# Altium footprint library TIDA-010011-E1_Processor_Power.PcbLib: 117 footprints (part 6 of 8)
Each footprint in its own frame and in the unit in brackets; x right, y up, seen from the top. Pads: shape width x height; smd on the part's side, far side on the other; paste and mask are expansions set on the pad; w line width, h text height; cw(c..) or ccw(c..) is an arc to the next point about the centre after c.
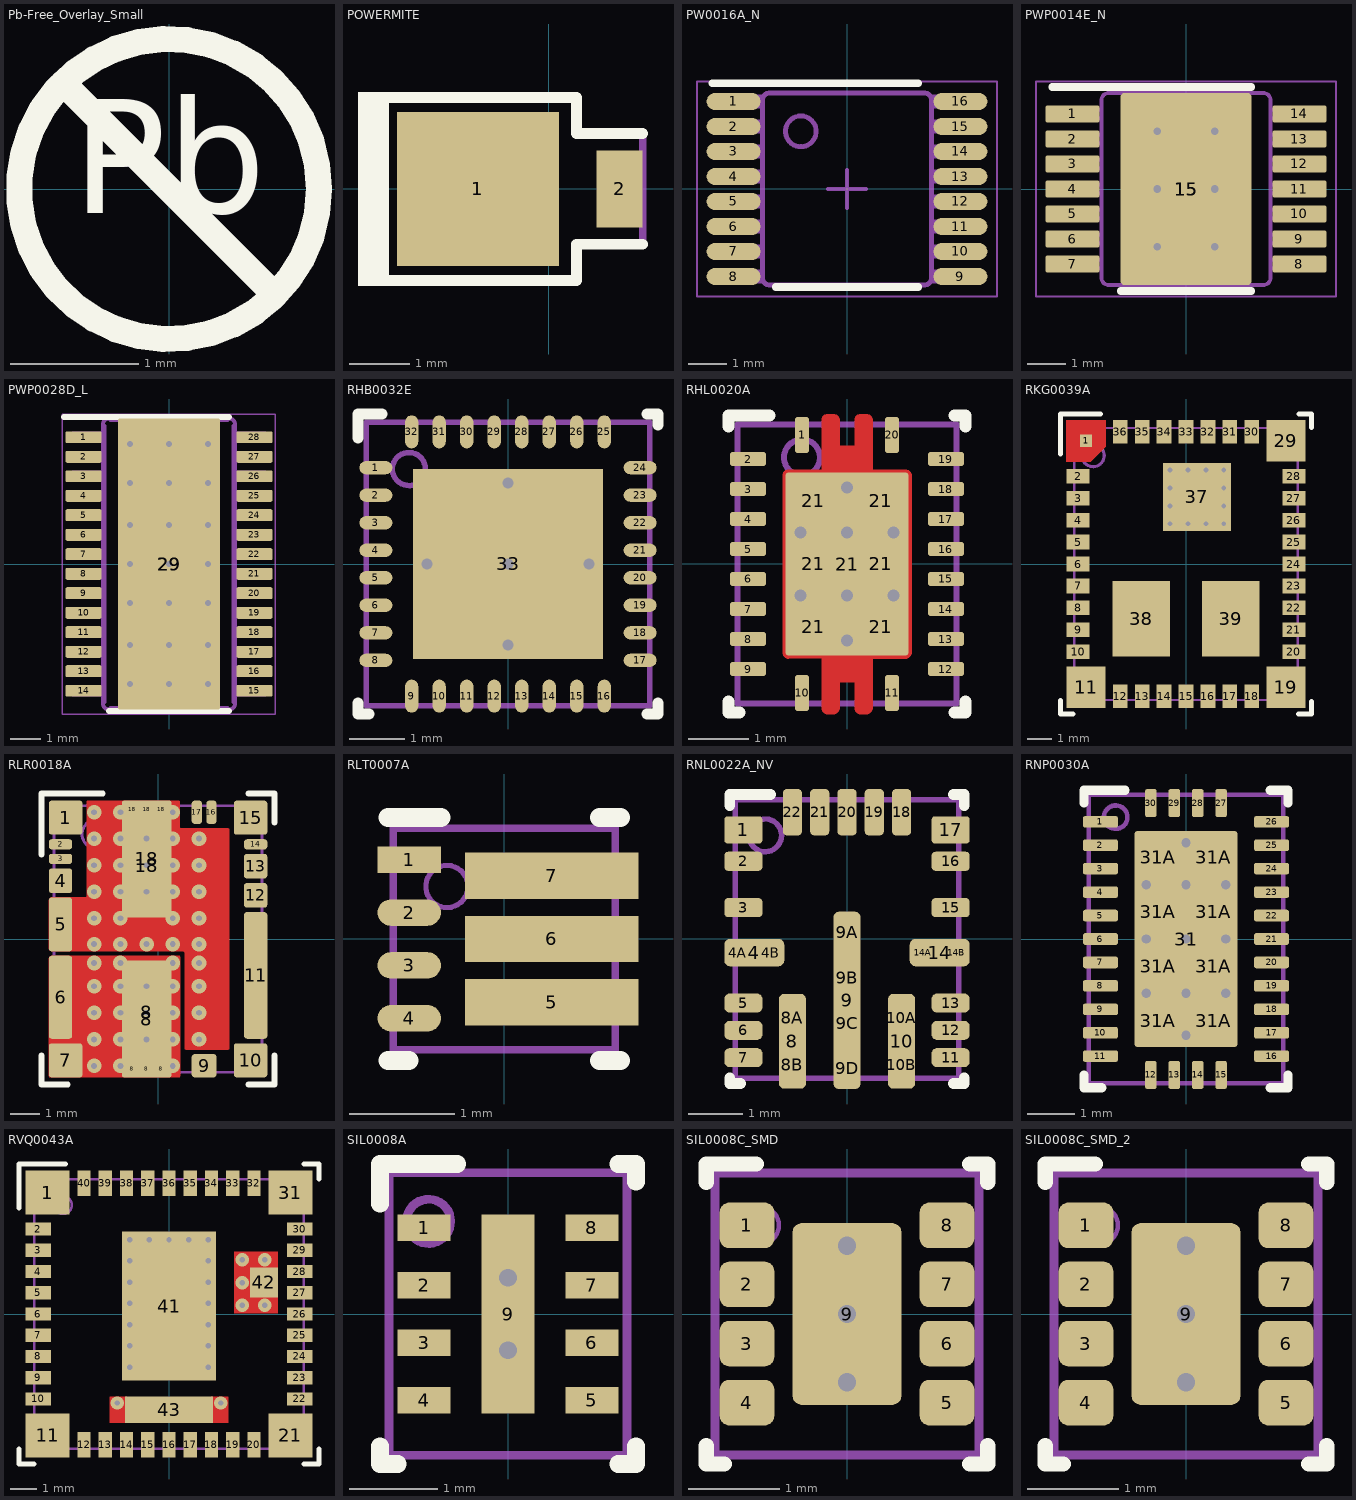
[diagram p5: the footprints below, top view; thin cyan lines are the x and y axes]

## Pb-Free_Overlay_Small [mm]
height 33
Top Overlay:
  circle w0.203: c0,0 r1.168
  lines w0.203: -0.826,0.826 0.826,-0.826
  text "Pb" at -0.752,-0.48 h1.52

## POWERMITE [mil] "On Semi recommended land pattern, 457-04.pdf Rev 04E dated 2008-11-26"
height 45.28
pads (2):
  rect 105x100 smd: 1(-46,0)
  rect 30x50 smd: 2(46,0)
Top Overlay:
  rectangle: -124,-63.02 -104,62.98
  lines w7: -109.7,-59.5 -19,-59.5 18,-59.5 18,-36 61,-36 ; -109.7,59.5 -19,59.5 18,59.5 18,36 61,36
Mechanical 5:
  rectangle: -124,-63.02 -104,62.98
  lines w5: -109.7,-59.5 -19,-59.5 18,-59.5 18,-36 61,-36 61,36 18,36 18,59.5 -19,59.5 -109.7,59.5
  text ".Designator" at -23,8 h20
3D body "PowerMite.stp": height 45.31, standoff 0, extent -94.48,-40.35 59.06,40.36

## PW0016A_N [mm] "TSOP, 16-Leads, Body 5x4.4mm, Pitch 0.65mm, IPC Medium Density"
height 1.2
pads (16):
  oval 1.4x0.45 smd: 1(-2.95,2.275) 2(-2.95,1.625) 3(-2.95,0.975) 4(-2.95,0.325) 5(-2.95,-0.325) 6(-2.95,-0.975) 7(-2.95,-1.625) 8(-2.95,-2.275) 9(2.95,-2.275) 10(2.95,-1.625) 11(2.95,-0.975) 12(2.95,-0.325) 13(2.95,0.325) 14(2.95,0.975) 15(2.95,1.625) 16(2.95,2.275)
Top Overlay:
  lines w0.2: -3.5,2.75 1.85,2.75 ; -1.85,-2.55 1.85,-2.55
Mechanical 5:
  drawing of 202 lines, arcs and shapes, not listed
  text ".Designator" at 0.004,0.787 h0.51
Mechanical 15:
  lines w0.05: -3.9,-2.8 -3.9,2.8 3.9,2.8 3.9,-2.8 -3.9,-2.8
  lines w0.1: -0.5,0 0.5,0 ; 0,-0.5 0,0.5
3D body "PW0016A.stp": height 1, standoff 0, extent -3.21,-2.5 3.21,2.5

## PWP0014E_N [mm] "TSOP, 14-Leads, Body 5x4.4mm, Pitch 0.65mm, Thermal Pad 3x3 mm, IPC Medium Density"
height 1.2
pads (17):
  rrect22% 1.4x0.45 smd: 1(-2.95,1.95) 2(-2.95,1.3) 3(-2.95,0.65) 4(-2.95,0) 5(-2.95,-0.65) 6(-2.95,-1.3) 7(-2.95,-1.95) 8(2.95,-1.95) 9(2.95,-1.3) 10(2.95,-0.65) 11(2.95,0) 12(2.95,0.65) 13(2.95,1.3) 14(2.95,1.95)
  rrect6% 3.4x5 smd paste-2 mask-2: 15(0,0)
  rrect50% 2.46x2.31 on Top Paste: 15(0,0)
  rrect50% 2.46x2.31 on Top Solder: 15(0,0)
via 0.75,-1.5 diameter 0.5 hole 0.2
via -0.75,-1.5 diameter 0.5 hole 0.2
via -0.75,1.5 diameter 0.5 hole 0.2
via 0.75,1.5 diameter 0.5 hole 0.2
via 0.75,0 diameter 0.5 hole 0.2
via -0.75,0 diameter 0.5 hole 0.2
Top Overlay:
  lines w0.2: -3.475,2.65 1.7,2.65 ; -1.7,-2.65 1.7,-2.65
Mechanical 5:
  lines w0.1: -2.2,-2.06 -3.209,-2.06 -3.209,-1.84 -2.2,-1.84 ; -2.2,-1.41 -3.209,-1.41 -3.209,-1.19 -2.2,-1.19 ; -2.2,-0.76 -3.209,-0.76 -3.209,-0.54 -2.2,-0.54 ; -2.2,-0.11 -3.209,-0.11 -3.209,0.11 -2.2,0.11 ; -2.2,0.54 -3.209,0.54 -3.209,0.76 -2.2,0.76 ; -2.2,1.19 -3.209,1.19 -3.209,1.41 -2.2,1.41 ; -2.2,1.84 -3.209,1.84 -3.209,2.06 -2.2,2.06 ; 2.2,-2.06 3.209,-2.06 3.209,-1.84 2.2,-1.84 ; 2.2,-1.41 3.209,-1.41 3.209,-1.19 2.2,-1.19 ; 2.2,-0.76 3.209,-0.76 3.209,-0.54 2.2,-0.54 ; 2.2,-0.11 3.209,-0.11 3.209,0.11 2.2,0.11 ; 2.2,0.54 3.209,0.54 3.209,0.76 2.2,0.76 ; 2.2,1.19 3.209,1.19 3.209,1.41 2.2,1.41 ; 2.2,1.84 3.209,1.84 3.209,2.06 2.2,2.06 ; -2.2,-2.3 ccw(c-2,-2.3) -2,-2.5 2,-2.5 ccw(c2,-2.3) 2.2,-2.3 2.2,2.3 ccw(c2,2.3) 2,2.5 -2,2.5 ccw(c-2,2.3) -2.2,2.3 -2.2,-2.3 ; -1.2,1.1 ccw(c-1.2,1.5) -1.2,1.9 ccw(c-1.2,1.5) -1.2,1.1
  text ".Designator" at -0.914,-0.279 h0.51
Mechanical 15:
  lines w0.05: -3.9,-2.8 -3.9,2.8 3.9,2.8 3.9,-2.8 -3.9,-2.8
  lines w0.1: -0.5,0 0.5,0 ; 0,-0.5 0,0.5
3D body "PWP0014A.stp": height 1, standoff 0, extent -3.209,-2.5 3.209,2.5

## PWP0028D_L [mm] "TSOP, 28-Leads, Body 9.7x4.4mm, Pitch 0.65mm, Exposed Pad, IPC High Density"
height 1.1
pads (31):
  rrect25% 1.2x0.4 smd: 1(-2.85,4.225) 2(-2.85,3.575) 3(-2.85,2.925) 4(-2.85,2.275) 5(-2.85,1.625) 6(-2.85,0.975) 7(-2.85,0.325) 8(-2.85,-0.325) 9(-2.85,-0.975) 10(-2.85,-1.625) 11(-2.85,-2.275) 12(-2.85,-2.925) 13(-2.85,-3.575) 14(-2.85,-4.225) 15(2.85,-4.225) 16(2.85,-3.575) 17(2.85,-2.925) 18(2.85,-2.275) 19(2.85,-1.625) 20(2.85,-0.975) 21(2.85,-0.325) 22(2.85,0.325) 23(2.85,0.975) 24(2.85,1.625) 25(2.85,2.275) 26(2.85,2.925) 27(2.85,3.575) 28(2.85,4.225)
  rrect3% 3.4x9.7 smd paste-1.7 mask-1.7: 29(0,0)
  rrect50% 2.4x6.46 on Top Paste: 29(0,0)
  rrect50% 2.4x6.46 on Top Solder: 29(0,0)
via -1.3,-2.7 diameter 0.5 hole 0.2
via 0,-2.7 diameter 0.5 hole 0.2
via 1.3,-2.7 diameter 0.5 hole 0.2
via -1.3,-4 diameter 0.5 hole 0.2
via 0,-4 diameter 0.5 hole 0.2
via 1.3,-4 diameter 0.5 hole 0.2
via 1.3,-1.3 diameter 0.5 hole 0.2
via 0,-1.3 diameter 0.5 hole 0.2
via -1.3,-1.3 diameter 0.5 hole 0.2
via 1.3,4 diameter 0.5 hole 0.2
via 0,4 diameter 0.5 hole 0.2
via -1.3,4 diameter 0.5 hole 0.2
via 1.3,2.7 diameter 0.5 hole 0.2
via 0,2.7 diameter 0.5 hole 0.2
via -1.3,2.7 diameter 0.5 hole 0.2
via -1.3,0 diameter 0.5 hole 0.2
via -1.3,1.3 diameter 0.5 hole 0.2
via 0,1.3 diameter 0.5 hole 0.2
via 1.3,1.3 diameter 0.5 hole 0.2
via 1.3,0 diameter 0.5 hole 0.2
via 0,0 diameter 0.5 hole 0.2
Top Overlay:
  lines w0.2: -3.5,4.9 2,4.9 ; -2,-4.9 2,-4.9
Mechanical 5:
  drawing of 350 lines, arcs and shapes, not listed
  text ".Designator" at -0.991,-0.203 h0.51
Mechanical 15:
  lines w0.05: -3.55,-5 -3.55,5 3.55,5 3.55,-5 -3.55,-5
  lines w0.1: -0.5,0 0.5,0 ; 0,-0.5 0,0.5
3D body "PWP0028B.stp": height 1, standoff 0, extent -3.21,-4.85 3.21,4.85

## RHB0032E [mm] "QFN, 32-Leads, Body 5x5mm, Pitch 0.5mm, Thermal Pad 3.45x3.45mm, TI Recommended"
height 1
pads (33):
  oval 0.6x0.24 smd: 1(-2.4,1.75) 2(-2.4,1.25) 3(-2.4,0.75) 4(-2.4,0.25) 5(-2.4,-0.25) 6(-2.4,-0.75) 7(-2.4,-1.25) 8(-2.4,-1.75) 17(2.4,-1.75) 18(2.4,-1.25) 19(2.4,-0.75) 20(2.4,-0.25) 21(2.4,0.25) 22(2.4,0.75) 23(2.4,1.25) 24(2.4,1.75)
  oval 0.24x0.6 smd: 9(-1.75,-2.4) 10(-1.25,-2.4) 11(-0.75,-2.4) 12(-0.25,-2.4) 13(0.25,-2.4) 14(0.75,-2.4) 15(1.25,-2.4) 16(1.75,-2.4) 25(1.75,2.4) 26(1.25,2.4) 27(0.75,2.4) 28(0.25,2.4) 29(-0.25,2.4) 30(-0.75,2.4) 31(-1.25,2.4) 32(-1.75,2.4)
  rect 3.45x3.45 smd paste-1.725: 33(0,0)
via 0,-1.475 diameter 0.5 hole 0.2
via 1.475,0 diameter 0.5 hole 0.2
via 0,0 diameter 0.5 hole 0.2
via -1.475,0 diameter 0.5 hole 0.2
via 0,1.475 diameter 0.5 hole 0.2
Top Overlay:
  lines w0.2: -2.725,-2.525 -2.725,-2.725 -2.525,-2.725 ; -2.725,2.29 -2.725,2.725 -2.29,2.725 ; 2.525,-2.725 2.725,-2.725 2.725,-2.525 ; 2.525,2.725 2.725,2.725 2.725,2.525
Top Paste:
  rectangle: 0.1,0.1 1.586,1.586
  region: -0.1,1.586 -1.586,1.586 -1.586,0.1 -0.1,0.1
  region: -0.1,-0.1 -1.586,-0.1 -1.586,-1.586 -0.1,-1.586
  rectangle: 0.1,-1.586 1.586,-0.1
Mechanical 5:
  circle w0.1: c-1.8,1.725 r0.3
  lines w0.1: -2.575,-2.575 2.575,-2.575 2.575,2.575 -2.575,2.575 -2.575,-2.575
  text ".Designator" at -1.854,-0.508 h0.51
3D body: height 1, standoff 0, extent -2.575,-2.575 2.575,2.575
3D body: height 1.01, standoff 0.5, extent -2.099,1.426 -1.501,2.024

## RHL0020A [mm] "QFN, 20-Leads, Body 4.5x3.5mm, Pitch 0.5mm, Thermal Pad 3.05x2.05mm, TI Recommended"
height 1
pads (27):
  rrect42% 0.24x0.6 smd: 1(-0.75,2.15) 10(-0.75,-2.15) 11(0.75,-2.15) 20(0.75,2.15)
  rrect42% 0.6x0.24 smd: 2(-1.65,1.75) 3(-1.65,1.25) 4(-1.65,0.75) 5(-1.65,0.25) 6(-1.65,-0.25) 7(-1.65,-0.75) 8(-1.65,-1.25) 9(-1.65,-1.75) 12(1.65,-1.75) 13(1.65,-1.25) 14(1.65,-0.75) 15(1.65,-0.25) 16(1.65,0.25) 17(1.65,0.75) 18(1.65,1.25) 19(1.65,1.75)
  rrect50% 0.92x0.85 on Top Paste: 21(-0.56,-1.05) 21(-0.56,0) 21(-0.56,1.05) 21(0.56,-1.05) 21(0.56,0) 21(0.56,1.05)
  rrect5% 2.05x3.05 smd paste-2 mask+0: 21(0,0)
via 0,0.525 diameter 0.5 hole 0.2
via -0.775,0.525 diameter 0.5 hole 0.2
via 0,1.275 diameter 0.5 hole 0.2
via 0.775,0.525 diameter 0.5 hole 0.2
via 0,-1.275 diameter 0.5 hole 0.2
via 0.775,-0.525 diameter 0.5 hole 0.2
via -0.775,-0.525 diameter 0.5 hole 0.2
via 0,-0.525 diameter 0.5 hole 0.2
Top Layer:
  region: -0.975,-1.575 -0.425,-1.575 -0.425,-2.4 -0.425,-2.42 -0.41,-2.457 -0.382,-2.485 -0.345,-2.5 -0.325,-2.5 -0.225,-2.5 -0.205,-2.5 -0.168,-2.485 -0.14,-2.457 -0.125,-2.42 -0.125,-2.4 -0.125,-1.975 0.125,-1.975 0.125,-2.4 0.125,-2.42 0.14,-2.457 0.168,-2.485 0.205,-2.5 0.225,-2.5 0.325,-2.5 0.345,-2.5 0.382,-2.485 0.41,-2.457 0.425,-2.42 0.425,-2.4 0.425,-1.575 0.975,-1.575 0.995,-1.575 1.032,-1.56 1.06,-1.532 1.075,-1.495 1.075,-1.475 1.075,1.475 1.075,1.495 1.06,1.532 1.032,1.56 0.995,1.575 0.975,1.575 0.425,1.575 0.425,2.4 0.425,2.42 0.41,2.457 0.382,2.485 0.345,2.5 0.325,2.5 0.225,2.5 0.205,2.5 0.168,2.485 0.14,2.457 0.125,2.42 0.125,2.4 0.125,1.975 -0.125,1.975 -0.125,2.4 -0.125,2.42 -0.14,2.457 -0.168,2.485 -0.205,2.5 -0.225,2.5 -0.325,2.5 -0.345,2.5 -0.382,2.485 -0.41,2.457 -0.425,2.42 -0.425,2.4 -0.425,1.575 -0.975,1.575 -0.995,1.575 -1.032,1.56 -1.06,1.532 -1.075,1.495 -1.075,1.475 -1.075,-1.475 -1.075,-1.495 -1.06,-1.532 -1.032,-1.56 -0.995,-1.575
Top Overlay:
  lines w0.2: -1.975,-2.29 -1.975,-2.475 -1.79,-2.475 ; -1.975,2.29 -1.975,2.475 -1.29,2.475 ; 1.79,-2.475 1.975,-2.475 1.975,-2.29 ; 1.79,2.475 1.975,2.475 1.975,2.29
Top Paste:
  region: -0.325,-2.45 -0.335,-2.45 -0.353,-2.442 -0.367,-2.428 -0.375,-2.41 -0.375,-2.4 -0.375,-1.725 -0.375,-1.715 -0.367,-1.697 -0.353,-1.683 -0.335,-1.675 -0.325,-1.675 0.325,-1.675 0.335,-1.675 0.353,-1.683 0.367,-1.697 0.375,-1.715 0.375,-1.725 0.375,-2.4 0.375,-2.41 0.367,-2.428 0.353,-2.442 0.335,-2.45 0.325,-2.45 0.225,-2.45 0.215,-2.45 0.197,-2.442 0.183,-2.428 0.175,-2.41 0.175,-2.4 0.175,-1.925 -0.175,-1.925 -0.175,-2.4 -0.175,-2.41 -0.183,-2.428 -0.197,-2.442 -0.215,-2.45 -0.225,-2.45
  region: -0.325,2.45 -0.335,2.45 -0.353,2.442 -0.367,2.428 -0.375,2.41 -0.375,2.4 -0.375,1.725 -0.375,1.715 -0.367,1.697 -0.353,1.683 -0.335,1.675 -0.325,1.675 0.325,1.675 0.335,1.675 0.353,1.683 0.367,1.697 0.375,1.715 0.375,1.725 0.375,2.4 0.375,2.41 0.367,2.428 0.353,2.442 0.335,2.45 0.325,2.45 0.225,2.45 0.215,2.45 0.197,2.442 0.183,2.428 0.175,2.41 0.175,2.4 0.175,1.925 -0.175,1.925 -0.175,2.4 -0.175,2.41 -0.183,2.428 -0.197,2.442 -0.215,2.45 -0.225,2.45
Mechanical 5:
  circle w0.1: c-0.75,1.775 r0.3
  lines w0.1: -1.825,-2.325 1.825,-2.325 1.825,2.325 -1.825,2.325 -1.825,-2.325
  text ".Designator" at 0.56,-0.021 h0.51
3D body "RHL0020A.stp": height 1.01, standoff 0.01, extent -1.75,-2.25 1.75,2.25

## RKG0039A [mm]
height 2.9
pads (39):
  rect 0.5x0.5 smd paste-0.25: 1(-4.1,5.05)
  rect 0.95x0.6 smd paste-0.025: 2(-4.425,3.6) 3(-4.425,2.7) 4(-4.425,1.8) 5(-4.425,0.9) 6(-4.425,0) 7(-4.425,-0.9) 8(-4.425,-1.8) 9(-4.425,-2.7) 10(-4.425,-3.6) 20(4.425,-3.6) 21(4.425,-2.7) 22(4.425,-1.8) 23(4.425,-0.9) 24(4.425,0) 25(4.425,0.9) 26(4.425,1.8) 27(4.425,2.7) 28(4.425,3.6)
  rect 1.6x1.7 smd paste-0.8: 11(-4.1,-5.05) 19(4.1,-5.05) 29(4.1,5.05)
  rect 0.6x0.95 smd paste-0.025: 12(-2.7,-5.425) 13(-1.8,-5.425) 14(-0.9,-5.425) 15(0,-5.425) 16(0.9,-5.425) 17(1.8,-5.425) 18(2.7,-5.425) 30(2.7,5.425) 31(1.8,5.425) 32(0.9,5.425) 33(0,5.425) 34(-0.9,5.425) 35(-1.8,5.425) 36(-2.7,5.425)
  rect 2.8x2.8 smd paste-1.387 mask-0.6: 37(0.45,2.75)
  rect 2.35x3.1 smd paste-1.537: 38(-1.83,-2.25) 39(1.84,-2.25)
via 0.817,1.65 diameter 0.5 hole 0.2
via 0.083,1.65 diameter 0.5 hole 0.2
via 1.55,3.117 diameter 0.5 hole 0.2
via 1.55,2.383 diameter 0.5 hole 0.2
via -0.65,3.117 diameter 0.5 hole 0.2
via -0.65,2.383 diameter 0.5 hole 0.2
via 0.083,3.85 diameter 0.5 hole 0.2
via 0.817,3.85 diameter 0.5 hole 0.2
via -0.65,1.65 diameter 0.5 hole 0.2
via -0.65,3.85 diameter 0.5 hole 0.2
via 1.55,3.85 diameter 0.5 hole 0.2
via 1.55,1.65 diameter 0.5 hole 0.2
Top Layer:
  region: -4.9,5.9 -3.3,5.9 -3.3,4.8 -3.9,4.2 -4.9,4.2
Top Overlay:
  lines w0.2: -5.15,-5.6 -5.15,-6.15 -4.625,-6.15 ; -5.15,4.5 -5.15,6.15 -3.5,6.15 ; 4.6,-6.15 5.15,-6.15 5.15,-5.625 ; 4.625,6.15 5.15,6.15 5.15,5.6
Top Paste:
  region: -3.325,-4.228 -4.565,-4.228 -4.565,-5.7 -3.325,-5.7
  rectangle: 3.325,-5.7 4.565,-4.228
  rectangle: 0.6,2.9 1.22,3.52
  region: 0.3,3.52 -0.32,3.52 -0.32,2.9 0.3,2.9
  region: 0.3,2.6 -0.32,2.6 -0.32,1.98 0.3,1.98
  rectangle: 0.6,1.98 1.22,2.6
  rectangle: 1.99,-2.1 2.88,-0.85
  region: 1.69,-0.85 0.8,-0.85 0.8,-2.1 1.69,-2.1
  region: 1.69,-2.4 0.8,-2.4 0.8,-3.65 1.69,-3.65
  rectangle: 1.99,-3.65 2.88,-2.4
  rectangle: -1.68,-2.1 -0.79,-0.85
  region: -1.98,-0.85 -2.87,-0.85 -2.87,-2.1 -1.98,-2.1
  region: -1.98,-2.4 -2.87,-2.4 -2.87,-3.65 -1.98,-3.65
  rectangle: -1.68,-3.65 -0.79,-2.4
  rectangle: 3.325,4.228 4.565,5.7
  region: -4.565,5.7 -3.325,5.7 -3.325,4.818 -3.915,4.228 -4.565,4.228
Mechanical 5:
  circle w0.127: c-3.81,4.445 r0.458
  lines w0.1: -4.575,-5.575 4.575,-5.575 4.575,5.575 -4.575,5.575 -4.575,-5.575
  text ".Designator" at 0.411,0.15 h0.51
3D body: height 2.9, standoff 0, extent -4.574,-5.574 4.574,5.574
3D body: height 2.91, standoff 2, extent -4.267,3.988 -3.353,4.902

## RLR0018A [mm] "B2QFN, Body 7x9mm"
height 4.1
pads (60):
  rrect17% 1.15x1.17 smd paste-1.15 mask-1.15: 1(-3.175,4.165) 7(-3.175,-4.165) 10(3.175,-4.165) 15(3.175,4.165)
  rrect57% 0.8x0.35 smd paste-0.05 mask-0.05: 2(-3.35,3.25) 3(-3.35,2.75) 14(3.35,3.25)
  rrect25% 0.8x0.85 smd paste-0.4 mask-0.4: 4(-3.35,2) 12(3.35,1.5) 13(3.35,2.5)
  rrect25% 0.8x1.85 smd paste-0.4 mask-0.4: 5(-3.35,0.5)
  rrect25% 0.8x2.85 smd paste-0.4 mask-0.4: 6(-3.35,-2)
  rrect50% 0.25x0.5 on Top Solder: 8(-0.895,-4.45) 8(-0.395,-4.45) 8(0.105,-4.45) 18(-0.895,4.45) 18(-0.395,4.45) 18(0.105,4.45)
  rrect8% 1.7x4.005 smd paste-2 mask-2: 8(-0.395,-2.748) 18(-0.395,2.748)
  rrect50% 1.6x3.48 on Top Solder: 8(-0.395,-2.521) 18(-0.395,2.519)
  rrect25% 0.85x0.8 smd paste-0.4 mask-0.4: 9(1.58,-4.35)
  rrect25% 0.8x4.35 smd paste-0.4 mask-0.4: 11(3.35,-1.25)
  rrect57% 0.35x0.8 smd paste-0.05 mask-0.05: 16(1.83,4.35) 17(1.33,4.35)
  rrect50% 0.265x0.25 on Top Paste: ""(-3.568,-3.75) ""(-3.568,3.75) ""(3.568,-3.75) ""(3.568,3.75)
  rrect50% 0.585x0.61 on Top Paste: ""(-2.943,-3.93) ""(-2.943,3.93) ""(2.943,-3.93) ""(2.943,3.93)
  rrect50% 0.25x0.265 on Top Paste: ""(-2.775,-4.568) ""(-2.775,4.568) ""(-0.895,-4.568) ""(-0.895,4.568) ""(-0.395,-4.568) ""(-0.395,4.568) ""(0.105,-4.568) ""(0.105,4.568) ""(2.775,-4.568) ""(2.775,4.568)
  rrect50% 0.67x0.71 on Top Paste: ""(-0.83,-3.9) ""(-0.83,-2.99) ""(-0.83,-2.08) ""(-0.83,-1.17) ""(-0.83,1.17) ""(-0.83,2.08) ""(-0.83,2.99) ""(-0.83,3.9) ""(0.04,-3.9) ""(0.04,-2.99) ""(0.04,-2.08) ""(0.04,-1.17) ""(0.04,1.17) ""(0.04,2.08) ""(0.04,2.99) ""(0.04,3.9)
via -2.195,-3.445 diameter 0.5 hole 0.2
via 1.405,-0.825 diameter 0.5 hole 0.2
via 1.405,-2.535 diameter 0.5 hole 0.2
via 1.405,-1.625 diameter 0.5 hole 0.2
via 1.405,-3.445 diameter 0.5 hole 0.2
via -2.195,-4.355 diameter 0.5 hole 0.2
via -2.195,-2.535 diameter 0.5 hole 0.2
via 1.405,3.445 diameter 0.5 hole 0.2
via 1.405,1.625 diameter 0.5 hole 0.2
via 1.405,2.535 diameter 0.5 hole 0.2
via 1.405,0.715 diameter 0.5 hole 0.2
via 1.405,-0.175 diameter 0.5 hole 0.2
via -2.195,3.445 diameter 0.5 hole 0.2
via -2.195,1.625 diameter 0.5 hole 0.2
via -2.195,2.535 diameter 0.5 hole 0.2
via -2.195,0.715 diameter 0.5 hole 0.2
via 0.505,0.715 diameter 0.5 hole 0.2
via -1.295,0.715 diameter 0.5 hole 0.2
via -1.295,2.535 diameter 0.5 hole 0.2
via -1.295,1.625 diameter 0.5 hole 0.2
via -1.295,3.445 diameter 0.5 hole 0.2
via 0.505,3.445 diameter 0.5 hole 0.2
via -0.395,3.445 diameter 0.5 hole 0.2
via -1.295,-3.445 diameter 0.5 hole 0.2
via -1.295,-1.625 diameter 0.5 hole 0.2
via -1.295,-2.535 diameter 0.5 hole 0.2
via 0.505,4.35 diameter 0.5 hole 0.2
via -1.295,4.35 diameter 0.5 hole 0.2
via -2.195,4.35 diameter 0.5 hole 0.2
via -1.295,-4.355 diameter 0.5 hole 0.2
via 0.505,-4.355 diameter 0.5 hole 0.2
via -2.195,-1.625 diameter 0.5 hole 0.2
via -1.295,-0.175 diameter 0.5 hole 0.2
via -2.195,-0.175 diameter 0.5 hole 0.2
via 0.505,-0.175 diameter 0.5 hole 0.2
via 0.505,-3.445 diameter 0.5 hole 0.2
via 0.505,-1.625 diameter 0.5 hole 0.2
via 0.505,-2.535 diameter 0.5 hole 0.2
via -1.295,-0.825 diameter 0.5 hole 0.2
via -2.195,-0.825 diameter 0.5 hole 0.2
via 0.505,1.625 diameter 0.5 hole 0.2
via -0.395,2.535 diameter 0.5 hole 0.2
via 0.505,2.535 diameter 0.5 hole 0.2
via -0.395,1.625 diameter 0.5 hole 0.2
via 0.505,-0.825 diameter 0.5 hole 0.2
via -0.395,-0.175 diameter 0.5 hole 0.2
via -0.395,-1.625 diameter 0.5 hole 0.2
via -0.395,-2.535 diameter 0.5 hole 0.2
via -0.395,-3.445 diameter 0.5 hole 0.2
Top Layer:
  region: -3.7,-4.75 -3.71,-4.75 -3.728,-4.742 -3.742,-4.728 -3.75,-4.71 -3.75,-4.7 -3.75,-0.675 -3.75,-0.655 -3.735,-0.618 -3.707,-0.59 -3.67,-0.575 -3.65,-0.575 0.71,-0.575 0.72,-0.575 0.738,-0.583 0.752,-0.597 0.76,-0.615 0.76,-0.625 0.76,-4.7 0.76,-4.71 0.752,-4.728 0.738,-4.742 0.72,-4.75 0.71,-4.75
  region: -3.65,-0.425 -3.67,-0.425 -3.707,-0.41 -3.735,-0.382 -3.75,-0.345 -3.75,-0.325 -3.75,1.325 -3.75,1.345 -3.735,1.382 -3.707,1.41 -3.67,1.425 -3.65,1.425 -2.5,1.425 -2.49,1.426 -2.472,1.433 -2.458,1.447 -2.451,1.465 -2.45,1.475 -2.45,4.7 -2.45,4.71 -2.442,4.728 -2.428,4.742 -2.41,4.75 -2.4,4.75 0.7,4.75 0.71,4.75 0.728,4.742 0.742,4.728 0.75,4.71 0.75,4.7 0.75,3.85 0.751,3.84 0.758,3.822 0.772,3.808 0.79,3.801 0.8,3.8 2.4,3.8 2.41,3.8 2.428,3.792 2.442,3.778 2.45,3.76 2.45,3.75 2.45,-3.75 2.45,-3.76 2.442,-3.778 2.428,-3.792 2.41,-3.8 2.4,-3.8 0.96,-3.8 0.95,-3.8 0.932,-3.792 0.918,-3.778 0.91,-3.76 0.91,-3.75 0.91,-0.475 0.909,-0.465 0.902,-0.447 0.888,-0.434 0.87,-0.426 0.86,-0.425
Top Overlay:
  lines w0.2: -4,-4 -4,-5 -3.1,-5 ; -4,2.9 -4,5 -1.9,5 ; 3.1,-5 4,-5 4,-4 ; 3.1,5 4,5 4,4
Top Paste:
  drawing of 7 lines, arcs and shapes, not listed
Top Solder:
  drawing of 11 lines, arcs and shapes, not listed
Mechanical 5:
  circle w0.1: c-2.1,3.6 r0.51
  lines w0.1: -3.575,-4.575 3.575,-4.575 3.575,4.575 -3.575,4.575 -3.575,-4.575
  text ".Designator" at -1.115,-0.501 h0.51
3D body: height 4.1, standoff 0, extent -3.575,-4.575 3.575,4.575
3D body: height 4.1, standoff 3.9, extent -2.609,3.091 -1.591,4.109

## RLT0007A [mm] "TI"
height 1
pads (7):
  rect 0.6x0.25 smd paste-0.2: 1(-0.9,0.75)
  oval 0.6x0.25 smd paste-0.2: 2(-0.9,0.25) 3(-0.9,-0.25) 4(-0.9,-0.75)
  rect 1.64x0.44 smd paste-0.22 mask-0.07: 5(0.45,-0.6) 6(0.45,0) 7(0.45,0.6)
Top Overlay:
  lines w0.18: -1.1,-1.15 -0.9,-1.15 ; -1.1,1.15 -0.6,1.15 ; 0.9,-1.15 1.1,-1.15 ; 0.9,1.15 1.1,1.15
Top Paste:
  circle w0.11: c-0.705,-0.75 r0.05
  circle w0.11: c-1.095,-0.75 r0.05
  circle w0.11: c-0.706,-0.25 r0.05
  circle w0.11: c-1.095,-0.25 r0.05
  circle w0.11: c-0.705,0.25 r0.05
  circle w0.11: c-1.095,0.25 r0.05
  rectangle: -0.3,0.45 0.35,0.75
  rectangle: -0.3,-0.15 0.35,0.15
  rectangle: -1.2,0.645 -0.6,0.855
  rectangle: -1.102,-0.855 -0.702,-0.645
  rectangle: -1.105,-0.355 -0.705,-0.145
  rectangle: -1.102,0.145 -0.702,0.355
  rectangle: 0.551,0.45 1.201,0.75
  rectangle: 0.55,-0.15 1.2,0.15
  rectangle: -0.3,-0.75 0.35,-0.45
  rectangle: 0.55,-0.75 1.2,-0.45
Mechanical 5:
  circle w0.05: c-0.543,0.497 r0.2
  lines w0.07: -1.05,-1.05 -1.05,1.05 1.05,1.05 1.05,-1.05 -1.05,-1.05
  text ".Designator" at -0.406,-0.388 h0.51
3D body "RLT0007A.stp": height 1, standoff 0, extent -1,-1 1,1

## RNL0022A_NV [mm] "VQFN, 22 pin, 0.5 mm pitch"
height 0.9
pads (34):
  rrect25% 0.7x0.5 smd paste-0.05 mask-0.05: 1(-1.9,2) 17(1.9,2)
  rrect40% 0.7x0.35 smd paste-0.05 mask-0.05: 2(-1.9,1.425) 3(-1.9,0.575) 15(1.9,0.575) 16(1.9,1.425)
  rrect40% 1.1x0.5 smd paste-0.25 mask-0.05: 4(-1.7,-0.25) 14(1.7,-0.25)
  rrect50% 0.4x0.4 on Top Paste: 4A(-2,-0.25) 4B(-1.4,-0.25) 14A(1.4,-0.25) 14B(2,-0.25)
  rrect57% 0.7x0.35 smd paste-0.05 mask-0.05: 5(-1.9,-1.175) 6(-1.9,-1.675) 7(-1.9,-2.175) 11(1.9,-2.175) 12(1.9,-1.675) 13(1.9,-1.175)
  rrect40% 0.5x1.74 smd paste-0.25 mask-0.05: 8(-1,-1.875) 10(1,-1.875)
  rrect50% 0.4x0.66 on Top Paste: 8A(-1,-1.445) 8B(-1,-2.305) 10A(1,-1.445) 10B(1,-2.305)
  rrect40% 0.5x3.25 smd paste-0.25 mask-0.05: 9(0,-1.125)
  rrect50% 0.4x0.63 on Top Paste: 9A(0,0.12) 9B(0,-0.71) 9C(0,-1.54) 9D(0,-2.37)
  rrect40% 0.35x0.85 smd paste-0.05 mask-0.05: 18(1,2.325) 19(0.5,2.325) 20(0,2.325) 21(-0.5,2.325) 22(-1,2.325)
Top Overlay:
  lines w0.2: -2.15,-2.55 -2.15,-2.65 -1.95,-2.65 ; -2.15,2.45 -2.15,2.65 -1.4,2.65 ; 1.95,-2.65 2.15,-2.65 2.15,-2.55 ; 1.95,2.65 2.15,2.65 2.15,2.45
Mechanical 5:
  circle w0.1: c-1.5,1.9 r0.3
  lines w0.1: -2.05,-2.55 2.05,-2.55 2.05,2.55 -2.05,2.55 -2.05,-2.55
  text ".Designator" at -1.524,-0.508 h0.51
3D body "RNL0022A.stp": height 0.9, standoff 0, extent -2,-2.5 2,2.5

## RNP0030A [mm] "QFN, 30-Leads, Body 6x4mm, Pitch 0.5mm, Thermal Pad 4.6x2.2mm"
height 0.8
pads (39):
  rrect40% 0.75x0.25 smd: 1(-1.825,2.5) 2(-1.825,2) 3(-1.825,1.5) 4(-1.825,1) 5(-1.825,0.5) 6(-1.825,0) 7(-1.825,-0.5) 8(-1.825,-1) 9(-1.825,-1.5) 10(-1.825,-2) 11(-1.825,-2.5) 16(1.825,-2.5) 17(1.825,-2) 18(1.825,-1.5) 19(1.825,-1) 20(1.825,-0.5) 21(1.825,0) 22(1.825,0.5) 23(1.825,1) 24(1.825,1.5) 25(1.825,2) 26(1.825,2.5)
  rrect40% 0.25x0.6 smd: 12(-0.75,-2.9) 13(-0.25,-2.9) 14(0.25,-2.9) 15(0.75,-2.9) 27(0.75,2.9) 28(0.25,2.9) 29(-0.25,2.9) 30(-0.75,2.9)
  rrect5% 2.2x4.6 smd paste-3: 31(0,0)
  rrect50% 0.98x0.96 on Top Paste: 31A(-0.59,-1.74) 31A(-0.59,-0.58) 31A(-0.59,0.58) 31A(-0.59,1.74) 31A(0.59,-1.74) 31A(0.59,-0.58) 31A(0.59,0.58) 31A(0.59,1.74)
via -0.85,1.16 diameter 0.5 hole 0.2
via -0.85,-1.16 diameter 0.5 hole 0.2
via 0,1.16 diameter 0.5 hole 0.2
via 0,-1.16 diameter 0.5 hole 0.2
via 0,2.05 diameter 0.5 hole 0.2
via 0.85,-1.16 diameter 0.5 hole 0.2
via 0.85,1.16 diameter 0.5 hole 0.2
via 0,-2.05 diameter 0.5 hole 0.2
via 0.85,0 diameter 0.5 hole 0.2
via 0,0 diameter 0.5 hole 0.2
via -0.85,0 diameter 0.5 hole 0.2
Top Overlay:
  lines w0.2: -2.175,-2.9 -2.175,-3.175 -1.8,-3.175 ; -2.175,2.9 -2.175,3.175 -1.3,3.175 ; 1.8,-3.175 2.175,-3.175 2.175,-2.9 ; 1.8,3.175 2.175,3.175 2.175,2.9
Mechanical 5:
  circle w0.1: c-1.5,2.6 r0.25
  lines w0.1: -2.075,-3.075 2.075,-3.075 2.075,3.075 -2.075,3.075 -2.075,-3.075
  text ".Designator" at -0.131,-0.811 h0.51
3D body "RNP0030A.stp": height 0.77, standoff -0.03, extent -2,-3 2,3

## RVQ0043A [mm]
height 4.4
pads (43):
  rect 1.65x1.65 smd paste-0.225: 1(-4.575,4.575) 11(-4.575,-4.575) 21(4.575,-4.575) 31(4.575,4.575)
  rect 0.95x0.5 smd paste-0.025: 2(-4.925,3.2) 3(-4.925,2.4) 4(-4.925,1.6) 5(-4.925,0.8) 6(-4.925,0) 7(-4.925,-0.8) 8(-4.925,-1.6) 9(-4.925,-2.4) 10(-4.925,-3.2) 22(4.925,-3.2) 23(4.925,-2.4) 24(4.925,-1.6) 25(4.925,-0.8) 26(4.925,0) 27(4.925,0.8) 28(4.925,1.6) 29(4.925,2.4) 30(4.925,3.2)
  rect 0.5x0.95 smd paste-0.025: 12(-3.2,-4.925) 13(-2.4,-4.925) 14(-1.6,-4.925) 15(-0.8,-4.925) 16(0,-4.925) 17(0.8,-4.925) 18(1.6,-4.925) 19(2.4,-4.925) 20(3.2,-4.925) 32(3.2,4.925) 33(2.4,4.925) 34(1.6,4.925) 35(0.8,4.925) 36(0,4.925) 37(-0.8,4.925) 38(-1.6,4.925) 39(-2.4,4.925) 40(-3.2,4.925)
  rect 3.55x5.6 smd paste-1.78 mask-2: 41(0,0.3)
  rect 1.05x1.12 smd paste-1 mask+0: 42(3.575,1.187)
  rect 3.3x1 smd paste-0.5 mask+0: 43(0,-3.6)
via 3.605,0.327 diameter 0.5 hole 0.2
via 2.755,0.327 diameter 0.5 hole 0.2
via -1.95,-3.35 diameter 0.5 hole 0.2
via 1.95,-3.35 diameter 0.5 hole 0.2
via 2.755,2.047 diameter 0.5 hole 0.2
via 3.605,2.047 diameter 0.5 hole 0.2
via 0,2.8 diameter 0.5 hole 0.2
via 0.74,2.8 diameter 0.5 hole 0.2
via 2.755,1.177 diameter 0.5 hole 0.2
via -0.74,2.8 diameter 0.5 hole 0.2
via -1.475,2.8 diameter 0.5 hole 0.2
via -1.475,-2 diameter 0.5 hole 0.2
via -1.475,-1.2 diameter 0.5 hole 0.2
via -1.475,-0.4 diameter 0.5 hole 0.2
via -1.475,0.4 diameter 0.5 hole 0.2
via -1.475,1.2 diameter 0.5 hole 0.2
via -1.475,2 diameter 0.5 hole 0.2
via 1.475,2 diameter 0.5 hole 0.2
via 1.475,1.2 diameter 0.5 hole 0.2
via 1.475,0.4 diameter 0.5 hole 0.2
via 1.475,-0.4 diameter 0.5 hole 0.2
via 1.475,-1.2 diameter 0.5 hole 0.2
via 1.475,-2 diameter 0.5 hole 0.2
via 1.475,2.8 diameter 0.5 hole 0.2
Top Layer:
  rectangle: 1.6,-4.1 2.25,-3.1
  rectangle: -2.25,-4.1 -1.6,-3.1
  rectangle: 2.925,0.027 4.1,0.762
  rectangle: 2.45,0.027 3.08,1.812
  rectangle: 2.45,1.712 4.1,2.347
Top Overlay:
  lines w0.2: -5.65,-5.1 -5.65,-5.65 -5.1,-5.65 ; 5.1,-5.65 5.65,-5.65 5.65,-5.1 ; 5.1,5.65 5.65,5.65 5.65,5.1
  lines w0.203: -5.65,4 -5.65,5.65 -3.9,5.65
Top Paste:
  rectangle: 0.5,-4.06 0.9,-3.13
  rectangle: -0.2,-4.06 0.2,-3.13
  rectangle: 1.2,-4.06 1.6,-3.13
  rectangle: -1.6,-4.06 -1.2,-3.13
  rectangle: -0.9,-4.06 -0.5,-3.13
  rectangle: -1.13,-1.59 -0.15,-1.02
  rectangle: 0.15,-1.59 1.13,-1.02
  rectangle: -1.13,-2.46 -0.15,-1.89
  rectangle: 0.15,-2.46 1.13,-1.89
  rectangle: -1.13,1.89 -0.15,2.46
  rectangle: 0.15,1.89 1.13,2.46
  rectangle: -1.13,1.02 -0.15,1.59
  rectangle: 0.15,1.02 1.13,1.59
  rectangle: 0.15,-0.72 1.13,-0.15
  rectangle: -1.13,-0.72 -0.15,-0.15
  rectangle: 0.15,0.15 1.13,0.72
  rectangle: -1.13,0.15 -0.15,0.72
  rectangle: 3.115,0.657 3.425,1.707
  rectangle: 3.725,0.657 4.035,1.707
Top Solder:
  rectangle: -1.176,-2.5 1.174,2.5
Mechanical 5:
  circle w0.1: c-3.989,4.1 r0.329
  lines w0.1: -5.075,-5.075 5.075,-5.075 5.075,5.075 -5.075,5.075 -5.075,-5.075
  text ".Designator" at -0.178,0.314 h0.51
Mechanical 15:
  lines w0.01: -5.175,4.1 -4.55,4.1 -3.975,4.675 -3.975,5.3 -5.175,5.3 -5.175,4.1
3D body: height 4.4, standoff 0, extent -5.074,-5.074 5.074,5.074
3D body: height 4.41, standoff 2, extent -4.317,3.772 -3.661,4.428

## SIL0008A [mm] "POS, 8-Leads, Body 2.5x3.0mm, Pitch 0.65mm, NSC Recommended"
height 1.5
pads (9):
  rect 0.6x0.3 smd mask+0.07: 1(-0.95,0.975) 2(-0.95,0.325) 3(-0.95,-0.325) 4(-0.95,-0.975) 5(0.95,-0.975) 6(0.95,-0.325) 7(0.95,0.325) 8(0.95,0.975)
  rect 0.6x2.25 smd paste-0.3 mask+0.07: 9(0,0)
via 0,-0.41 diameter 0.5 hole 0.2
via 0,0.41 diameter 0.5 hole 0.2
Top Overlay:
  lines w0.2: -1.45,-1.5 -1.45,-1.7 -1.25,-1.7 ; -1.45,1.25 -1.45,1.7 -0.575,1.7 ; 1.25,-1.7 1.45,-1.7 1.45,-1.5 ; 1.25,1.7 1.45,1.7 1.45,1.5
Top Paste:
  rectangle: -0.3,-0.308 0.3,0.308
  rectangle: -0.3,0.508 0.3,1.125
  rectangle: -0.3,-1.125 0.3,-0.508
Mechanical 5:
  circle w0.1: c-0.9,1.05 r0.25
  lines w0.1: -1.35,-1.6 1.35,-1.6 1.35,1.6 -1.35,1.6 -1.35,-1.6
  text ".Designator" at 0.62,0.31 h0.51
3D body "SIL0008A_ASM.stp": height 1.43, standoff 0.02, extent -1.3,-1.5 1.3,1.5

## SIL0008C_SMD [mm] "Solder Mask Defined pads"
height 1.33
pads (9):
  rrect40% 0.6x0.5 smd paste-0.05 mask-0.05: 1(-1.1,0.975) 2(-1.1,0.325) 3(-1.1,-0.325) 4(-1.1,-0.975) 5(1.1,-0.975) 6(1.1,-0.325) 7(1.1,0.325) 8(1.1,0.975)
  rrect17% 1.2x2 smd paste-0.6 mask-0.05: 9(0,0)
via 0,0 diameter 0.5 hole 0.2
via 0,-0.75 diameter 0.5 hole 0.2
via 0,0.75 diameter 0.5 hole 0.2
Top Overlay:
  lines w0.17: -1.55,-1.45 -1.55,-1.65 -1.35,-1.65 ; -1.55,1.45 -1.55,1.65 -1,1.65 ; 1.35,-1.65 1.55,-1.65 1.55,-1.45 ; 1.35,1.65 1.55,1.65 1.55,1.45
Top Paste:
  rectangle: -0.52,-0.95 0.52,-0.1
  rectangle: -0.52,0.1 0.52,0.95
Mechanical 5:
  circle w0.05: c-0.95,0.975 r0.202
  lines w0.1: -1.45,-1.55 -1.45,1.55 1.45,1.55 1.45,-1.55 -1.45,-1.55
  text ".Designator" at -0.551,-0.206 h0.51
3D body "SIL0008C.stp": height 1.31, standoff 0, extent -1.4,-1.5 1.4,1.5

## SIL0008C_SMD_2 [mm]
pads (9):
  rrect40% 0.6x0.5 smd paste-0.05 mask-0.05: 1(-1.1,0.975) 2(-1.1,0.325) 3(-1.1,-0.325) 4(-1.1,-0.975) 5(1.1,-0.975) 6(1.1,-0.325) 7(1.1,0.325) 8(1.1,0.975)
  rrect17% 1.2x2 smd paste-0.6 mask-0.05: 9(0,0)
via 0,0 diameter 0.5 hole 0.2
via 0,-0.75 diameter 0.5 hole 0.2
via 0,0.75 diameter 0.5 hole 0.2
Top Overlay:
  lines w0.17: -1.55,-1.45 -1.55,-1.65 -1.35,-1.65 ; -1.55,1.45 -1.55,1.65 -1,1.65 ; 1.35,-1.65 1.55,-1.65 1.55,-1.45 ; 1.35,1.65 1.55,1.65 1.55,1.45
Top Paste:
  rectangle: -0.52,-0.95 0.52,-0.1
  rectangle: -0.52,0.1 0.52,0.95
Mechanical 5:
  circle w0.05: c-0.95,0.975 r0.202
  lines w0.1: -1.45,-1.55 -1.45,1.55 1.45,1.55 1.45,-1.55 -1.45,-1.55
  text ".Designator" at -0.151,0.638 h0.51
3D body "SIL0008C.stp": height 1.31, standoff 0, extent -1.4,-1.5 1.4,1.5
